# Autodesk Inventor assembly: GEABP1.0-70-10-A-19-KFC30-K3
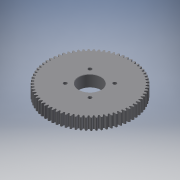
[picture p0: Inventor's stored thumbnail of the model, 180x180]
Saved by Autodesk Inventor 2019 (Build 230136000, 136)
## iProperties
Category: PARTsolutions
Company: MISUMI
Created: 2022-11
Part Number: GEABP1.0-70-10-A-19-KFC30-K3
Catalog Web Link: www.cadenas.de
Description: GEABM, GEABMS, GEABMT, GEABP, GEABPS, GEABPT, GEABA, GEABAS, GEABAT-Plastic Spur Gears - Pressure Angle 20 Degrees, Module 0.5/0.8/1.0/1.5/2.0/2.5/3.0
Vendor: MISUMI
Document SubType Name: Assembly
Designer: psAdmin
Manufacturer: MISUMI
Mass: 35.1523 g
Surface Area: 122.756 cm^2
Volume: 35.1523 cm^3
Density: 1 g/cm^3
Title: GEABP1.0-70-10-A-19-KFC30-K3
Author: Cadenas PARTsolutions
Comments: Plastic Spur Gears - Pressure Angle 20 Degrees, Module 0.5/0.8/1.0/1.5/2.0/2.5/3.0
PSOL_IDENT_0: {$CADENAS_DATA/23d-libs/misumi/metric/54_spur_gears/geabms20_asmtab.prj},415 {VTYP=3D},{STYP=ASSTAB}
PSOL_IDENT_1: ,{NB=GEABP1.0-70-10-A-19-KFC30-K3},{LINA=GEABP1.0-70-10-A-19-KFC30-K3},{NN=GEABM, GEABMS, GEABMT, GE
PSOL_IDENT_2: ABP, GEABPS, GEABPT, GEABA, GEABAS, GEABAT},{DATE=16.08.2021 10:08:31},{GEOMDATE=16.08.2021 10:08:28
PSOL_IDENT_3: },{VERSION=},{LINEID=30},{WBVAR=MATSG,MATCR,NT,B,TS,PS,ALT1,ALT2,TPC,ALT11,ALT10,BS,ALT3,Z,J,ALT4,Q,
PSOL_IDENT_4: R,S,T,ALT5,LFC,LTC,MALT5,ALT6,KFC,KTC,K},{WBNUMERIC=NT,B,BS,Z,J,Q,R,S,T,LFC,LTC,KFC,KTC,K}  {NB=GEAB
PSOL_IDENT_5: P1.0-70-10-A-19-KFC30-K3},{LINA=GEABP1.0-70-10-A-19-KFC30-K3},{KT=DUMMY},{PN=GEABP1.0-70-10-A-19-KFC
PSOL_IDENT_6: 30-K3},{TYPE=GEABP},{MATSG=PW},{MATSGALG='MCN','MC Nylon','PW','Polyacetal White','PB','Polyacetal B
PSOL_IDENT_7: lue'},{MATCR=},{MATCRALG='','-','S45C','1045 Carbon Steel','SUS304','304 Stainless Steel'},{MOD=1.0}
PSOL_IDENT_8: ,{MOD1=1.0},{NT=70},{NTALG=15,16,18,20,22,24,25,26,28,30,32,35,36,40,45,48,50,55,60,70,75,80,90,100,
PSOL_IDENT_9: 120},{B=10},{BALG=10,15},{TS=A},{TSALG='A','A','B','B'},{TSPN=-A},{PS=19},{PSALG='10','10','11','11'
PSOL_IDENT_10: ,'12','12','13','13','14','14','15','15','16','16','17','17','18','18','19','19','20','20','21','21'
PSOL_IDENT_11: ,'22','22','23','23','24','24','25','25','26','26','27','27','28','28'},{PSCRL='10','10','11','11','
PSOL_IDENT_12: 12','12','13','13','14','14','15','15','16','16','17','17','18','18','19','19','20','20','21','21','
PSOL_IDENT_13: 22','22','23','23','24','24','25','25','26','26','27','27','28','28'},{PSCRW='10','10','12','12','15'
PSOL_IDENT_14: ,'15','20','20'},{DD=70.0},{DD05=35},{DD08=56},{DD10=70},{DD15=105},{DD20=0},{DD25=0},{DD30=0},{D=72
PSOL_IDENT_15: .0},{D05=36},{D08=57.6},{D10=72},{D15=108},{D20=0},{D25=0},{D30=0},{G=67.50},{G05=33.75},{G08=54},{G
PSOL_IDENT_16: 10=67.5},{G15=101.25},{G20=0},{G25=0},{G30=0},{H=0.0},{L=0},{LL1=0},{LL2=0.0},{M=-},{M3D=0},{P=19.00
PSOL_IDENT_17: },{DD1=0},{CIFR=15},{CIFM=0},{CIFK=0},{CIFTAP=0},{SCREW=0.000},{SCREWL=0.000},{ALT1=},{ALT1ALG='','N
PSOL_IDENT_18: ot applicable'},{ALT1PN=},{ALT2=},{ALT2ALG='','Not applicable'},{TPC=N/A},{TPCALG='N/A'},{ALT2PN=},{
PSOL_IDENT_19: KC=0},{ALT11=},{ALT11ALG='','Not applicable'},{ALT11PN=},{DEG=0},{ALT10=},{ALT10ALG= '','Not applica
PSOL_IDENT_20: ble' },{ALT10PN=},{BS=0.0},{BSALG=0},{BSMIN=3.000},{BSMINALG=3},{BSMAX=0},{LL13D=0},{LL23D=0},{ALT3=
PSOL_IDENT_21: },{ALT3ALG= '','w/o Stepped Hole','DHL','with DHL (Stepped Hole)','DHR','with DHR (Stepped Hole)' },
PSOL_IDENT_22: {ALT3PN=},{ZJPN=},{ALT31=1},{ALT32=1},{Z=0},{ZALG=0},{ZMINL=21},{ZMAXL=63},{ZMINR=21},{ZMAXR=63},{ZP
PSOL_IDENT_23: N=},{J=0.0},{JALG=0},{JMIN=2},{JMAX=0},{JPN=},{ALT4=},{ALT4ALG= '','w/o WDH (Both Ends Stepped Hole)'
PSOL_IDENT_24: ,'WDH','with WDH (Both Ends Stepped Hole)' },{ALT4PN=},{QRSTPN=},{LB=10.000},{Q=0},{QALG=0},{QMIN=21
PSOL_IDENT_25: },{QMAX=63},{QPN=},{R=0},{RALG=0},{RMIN=21},{RMAX=63},{RPN=},{S=0},{SALG=0},{SMIN=3},{SMAX=4},{SPN=}
PSOL_IDENT_26: ,{T=0},{TALG=0},{TMIN=3},{TMAX=0},{TPN=},{ALT5=},{ALT5ALG= '','w/o Side Slotted Hole','LFC','with LF
PSOL_IDENT_27: C (Side Slotted Hole)','LTC','with LTC (Side Slotted Hole)' },{LFC=0},{LFCALG=0},{LTC=0},{LTCALG=0},
PSOL_IDENT_28: {LPCDMIN=27},{LPCDMAX=60},{LCMAX=63},{MALT5=N/A},{MALT5ALG= 'N/A' },{LCMAX2=60},{C=0.0},{ALT5PN=},{A
PSOL_IDENT_29: LT6=KFC},{ALT6ALG= '','w/o Side Through Hole','KFC','with KFC (Side Through Hole)','KTC','with KTC (
PSOL_IDENT_30: Side Through Hole)' },{ALT6PN=-KFC},{KFTCPN=30-K3},{KFC=30},{KFCALG=[26:60/1]},{KFCPN=30},{KTC=0},{K
PSOL_IDENT_31: TCALG=[0]},{KTCPN=},{KPCDMIN1=26},{KPCDMAX1=-7},{KPCDMIN2=7},{KPCDMAX2=60},{K=3.0},{KALG=[3:6/0.5]},
PSOL_IDENT_32: {KPCD=30},{KPN=-K3},{AG=0},{LBS=10},{PCD=30},{SHN=4},{SHDEG1=45},{SHDEG2=90},{PZQRDD2=19},{PPATH=gea
PSOL_IDENT_33: bms20/geabms20_asmtpl.prj}
NB: GEABP1.0-70-10-A-19-KFC30-K3
NN: GEABM, GEABMS, GEABMT, GEABP, GEABPS, GEABPT, GEABA, GEABAS, GEABAT
NT: 70
NBSYN: $PN.
LINA: GEABP1.0-70-10-A-19-KFC30-K3
CATALOG: Misumi
PN: GEABP1.0-70-10-A-19-KFC30-K3
MATSG: Polyacetal White
MATCR: -
MOD: 1.0
B: 10
TS: A
PS: 19
DD: 70
D: 72
G: 67.5
H: 0
L: 0
LL1: 0
LL2: 0
M: -
DD1: 0
ALT1: Not applicable
ALT2: Not applicable
TPC: N/A
ALT11: Not applicable
ALT10: Not applicable
BS: 0
ALT3: w/o Stepped Hole
Z: 0
J: 0
ALT4: w/o WDH (Both Ends Stepped Hole)
Q: 0
R: 0
S: 0
T: 0
ALT5: w/o Side Slotted Hole
LFC: 0
LTC: 0
MALT5: N/A
C: 0
ALT6: with KFC (Side Through Hole)
KFC: 30
KTC: 0
K: 3
SUPPLIER: MISUMI
ARTICLENO: GEABP1.0-70-10-A-19-KFC30-K3
BOMINFO: GEABP1.0-70-10-A-19-KFC30-K3
CREATOR: CADENAS GmbH
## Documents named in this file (2)
- e:\temp\worker_COMMON_10\temp\tmp_5204_342_tFofn\format_0\GEABP1_0-70-10-A-19-KFC30-K3.iam
- e:\temp\worker_COMMON_10\temp\tmp_5204_342_tFofn\format_0\GEABP1_0-70-10-A-19-KFC30-K3_b.ipt
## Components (1 placed, 1 different names)
1. GEABP1_0-70-10-A-19-KFC30-K3_b:1
